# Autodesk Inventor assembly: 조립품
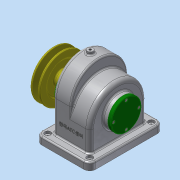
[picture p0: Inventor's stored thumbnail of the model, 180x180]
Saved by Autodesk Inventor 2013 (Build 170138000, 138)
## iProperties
Created: 2017-11
Part Number: 조립품
Document SubType Name: Assembly
Designer: Administrator
Author: Administrator
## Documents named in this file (14)
- C:\Users\Administrator\Desktop\471107V1027\조립품.iam
- C:\Users\Administrator\Desktop\471107V1027\본체.ipt
- C:\Users\Administrator\Desktop\471107V1027\V-벨트풀리.ipt
- C:\Users\Administrator\Desktop\471107V1027\뒤커버.ipt
- C:\Users\Administrator\Desktop\471107V1027\멈춤나사 - M4 x 10.ipt
- 멈춤나사 - M4 x 10.ipt
- C:\Users\Administrator\Desktop\471107V1027\베어링 6002.ipt
- C:\Users\Administrator\Desktop\471107V1027\볼트 M3 x 8.ipt
- C:\Users\Administrator\Desktop\471107V1027\스퍼기어.ipt
- C:\Users\Administrator\Desktop\471107V1027\앞커버.ipt
- C:\Users\Administrator\Desktop\471107V1027\오일 실 15 30 7.ipt
- C:\Users\Administrator\Desktop\471107V1027\축.ipt
- C:\Users\Administrator\Desktop\471107V1027\키 - 5 x 5 x 18.ipt
- C:\Users\Administrator\Desktop\471107V1027\키 - 6 x 6 x 22.ipt
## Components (1 placed, 1 different names)
1. V-벨트풀리:1
